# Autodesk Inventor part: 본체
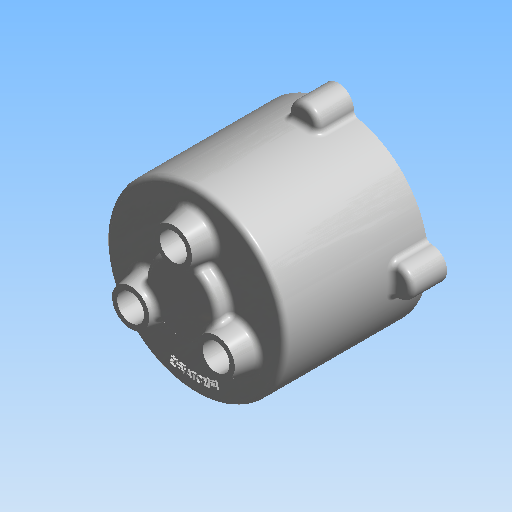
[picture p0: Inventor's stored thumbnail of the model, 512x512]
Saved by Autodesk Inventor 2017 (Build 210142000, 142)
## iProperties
Created: 2021-07
Part Number: 본체
Document SubType Name: 모델링
Designer: mdu
Material: 알루미늄 6061
Density: 1 g/cm^3
Appearance: 알루미늄 - 평지
변환 표준: STEP AP214IS
파일 이름: C:\Users\SeoGD\Desktop\?쒗뿕\紐몄껜.stp
전처리기: Build: 253, Release: 2010 SP1 - Date: Wed 07/29/2009
전송 단위: 밀리미터
불확실성: 0.01
Author: mdu
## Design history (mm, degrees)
sketch "스케치2"
  geometry: C1 r 50 at (0, 0); 1 further point
  constraints: 1 centre point, 1 coincident
  dimensions: "d9" = 100 diameter of C1
extrude "돌출2" new body sketch "스케치2" distance "d10" = 80; taper "d11" = 0 deg
feature "쉘1" dims "d12" = 5
sketch "스케치3" dims "d13" = 55
  geometry: C1 r 7.5 at (0, 27.5); C2 r 12.5 at (0, 27.5); 2 further points
  constraints: 2 centre point, 2 coincident, 2 vertical alignment, 2 other
  dimensions: "d14" = 15 diameter of C1; "d15" = 25 diameter of C2
extrude "돌출3" join sketch "스케치3" distance "d16" = 12; taper "d17" = -10 deg
sketch "스케치4"
  geometry: L1 (0, 0)-(0, 88); L2 (0, 70)-(14, 70); L3 (-45, 75)-(45, 75) reference; L4 (-50, 80)-(50, 80) reference; L5 (14, 70)-(14, 75); L6 (20, 80)-(20, 88); L7 (20, 88)-(0, 88); L8 (20, 80)-(14, 75)
  constraints: 12 end point, 3 point on line, 2 perpendicular, 1 vertical
  dimensions: "d34" = 40 diameter of L6 L1; "d35" = 90 deg angle of L5 L3; "d36" = 5 distance between parallel lines of L2 L3; "d37" = 8 distance between parallel lines of L7 L4; "d51" = 28 diameter of L5.end L1
revolve "회전1" sketch "스케치4" stored, may be unused: angle "d38" = 90 deg
hole "구멍3" diameter "d41" = 15; stored, may be unused: countersink angle "d45" = 90 deg, drill point angle "d47" = 0 deg; dims "d39" = 10, "d40" = 10, "d42" = 6, "d43" = 22, "d44" = 13, "d46" = 15
chamfer "모따기2" distance "d48" = 1; stored, may be unused: second distance "d49" = 2, angle "d50" = 45 deg
fillet "모깎기4" dims "d78" = 3
hole "구멍2" diameter "d20" = 15; stored, may be unused: countersink angle "d24" = 90 deg, drill point angle "d26" = 118 deg; dims "d21" = 6, "d22" = 25, "d23" = 1, "d25" = 15, "d76" = 10, "d77" = 10
chamfer "모따기1" distance "d27" = 1; stored, may be unused: second distance "d28" = 2, angle "d29" = 45 deg
sketch "스케치9"
  geometry: C1 r 12.5 at (0, 0) reference; C2 r 12.5 at (-23.816, -41.25) reference; C3 r 12.5 at (23.816, -41.25) reference; 1 further point
extrude "돌출5" cut sketch "스케치9" stored distance "d79" = 10; taper "d80" = 0 deg
fillet "모깎기1" dims "d52" = 3
fillet "모깎기2" dims "d53" = 3, "d72" = 0.2
sketch "스케치5"
  geometry: A1 r 50 centre (0, 0) between (50, 0) and (-8.074, 49.344) reference; A2 r 8.5 centre (0, 52) between (8.074, 49.344) and (-8.074, 49.344); 1 further point
  constraints: 5 point on circle, 1 centre point, 1 horizontal alignment
  dimensions: "d54" = 90 deg dimension on point (0, 0) A2.centre A1.start; "d55" = 52 distance of A2.centre point (0, 0); "d56" = 17 diameter of A2
extrude "돌출4" join sketch "스케치5" distance "d57" = 20; taper "d58" = 0 deg
fillet "모깎기3" dims "d59" = 3
hole "구멍4" diameter "d62" = 4.134; stored, may be unused: countersink angle "d66" = 90 deg, drill point angle "d68" = 118 deg; dims "d60" = 10, "d61" = 10, "d63" = 12, "d64" = 22, "d65" = 13, "d67" = 15
sketch "스케치6"
  geometry: C1 r 47 at (0, 0) reference; C2 r 42.5 at (0, 0); 1 further point
  constraints: 1 centre point, 1 coincident, 1 other
  dimensions: "d73" = 85 diameter of C2
feature "엠보싱1" sketch "스케치6" dims "d34" = 40, "d35" = 90 deg, "d36" = 5, "d37" = 8, "d51" = 28, "d74" = 1, "d75" = 0
node "솔리드1"
node "솔리드 본체"
node "곡면 본체"
pattern_circular "원형 패턴1" dims angle "d31" = 360 deg
pattern_circular "원형 패턴2" dims angle "d70" = 360 deg
node "솔리드2"
